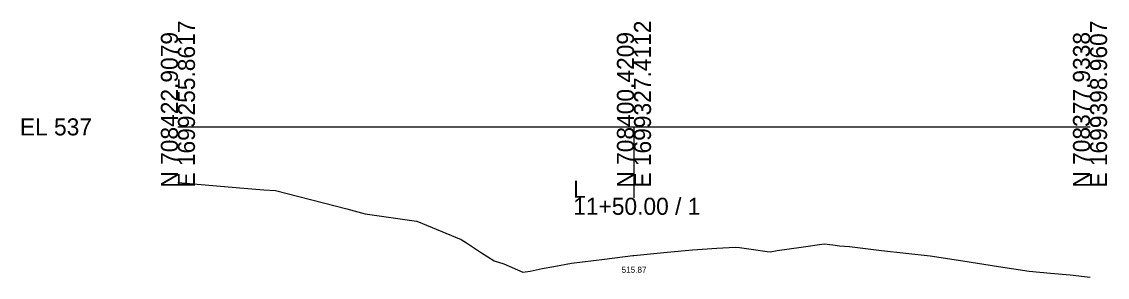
# Model space of a CAD drawing. Extents: x -63 to 1153, y -24 to 9522.
# Drawn here: x -25.7 to 152.8, y 475.3 to 517.3 of the extents above; entities that cross this region are included whole.
import ezdxf

# ---------------------------------------------------------------- set-up
doc = ezdxf.new("R2010")
doc.units = 0
for name, color, linetype in [('Default', 7, 'Continuous'), ('Exist Cross Section Cell', 7, 'Continuous'), ('Exist XS Center Line Elevation Label', 7, 'Continuous'), ('Exist XS Ground Line', 7, 'Continuous')]:
    doc.layers.add(name, color=color, linetype=linetype)

msp = doc.modelspace()

# ---------------------------------------------------------------- linework, layer by layer
at = {"layer": 'Exist Cross Section Cell'}
for p, q in [((0, 500), (75, 500)), ((75, 500), (150, 500)), ((75, 500), (75, 488.34))]:
    msp.add_line(p, q, dxfattribs=at)
at = {"layer": 'Exist XS Ground Line'}
msp.add_lwpolyline([(0, 490.83), (10.81, 489.91), (14.1, 489.63), (16.06, 489.56), (27.76, 486.5), (30.78, 485.68), (39.25, 484.49), (39.26, 484.49), (39.26, 484.48), (39.27, 484.48), (46.6, 481.49), (47.44, 480.93), (49.94, 479.29), (52.03, 477.95), (53.57, 477.45), (56.72, 476.09), (57.95, 476.26), (59.91, 476.69), (61.83, 477.06), (64.75, 477.57), (70.15, 478.26), (74.83, 478.85), (75, 478.87), (80.47, 479.37), (84.6, 479.76), (88.6, 480.05), (91.62, 480.21), (92.37, 480.14), (94.68, 479.81), (96.92, 479.52), (97.41, 479.43), (98.56, 479.66), (102.49, 480.24), (106.3, 480.78), (107.72, 480.6), (108.79, 480.45), (110.43, 480.32), (115.71, 479.68), (123.69, 478.8), (129.11, 477.95), (134.95, 477.01), (139.97, 476.27), (143.5, 475.96), (146.71, 475.67), (150, 475.26)], dxfattribs=at)

# ---------------------------------------------------------------- texts
at = {"layer": 'Default'}
msp.add_text('-', height=0.0001, dxfattribs=at).set_placement((0, 500))
at = {"layer": 'Exist Cross Section Cell'}
for s, p in [('E 1699255.8617', (2.8, 490)), ('E 1699327.4112', (77.8, 490)), ('E 1699398.9607', (152.8, 490)), ('N 708422.9079', (0, 490)), ('N 708400.4209', (75, 490)), ('N 708377.9338', (150, 490))]:
    msp.add_text(s, height=2.8, rotation=90, dxfattribs=at).set_placement(p)
for s, p in [('EL 537', (-26, 498.6)), ('L', (65, 488.34)), ('11+50.00 / 1', (65, 485.54))]:
    msp.add_text(s, height=2.8, dxfattribs=at).set_placement(p)
at = {"layer": 'Exist XS Center Line Elevation Label'}
msp.add_text('515.87', height=1, dxfattribs=at).set_placement((72.97, 476))

doc.saveas('drawing.dxf')
